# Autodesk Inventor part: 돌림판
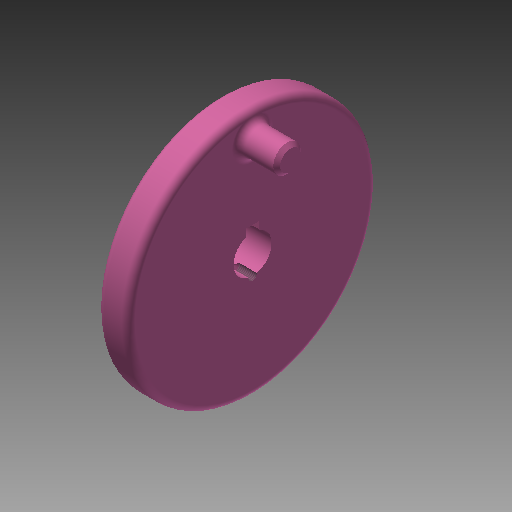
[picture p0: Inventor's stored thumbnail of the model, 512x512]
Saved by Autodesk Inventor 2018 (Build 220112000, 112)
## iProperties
Created: 2019-09
Part Number: 돌림판
Material: 알루미늄 6061
Document SubType Name: Modeling
Designer: mduedu
Density: 2.71 g/cm^3
Mass: 83.7231 g
Surface Area: 107.333 cm^2
Volume: 30.8941 cm^3
Appearance: 분홍색
Author: mduedu
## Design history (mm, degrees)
sketch "스케치1"
  geometry: L1 (0, 0)-(9, 0); L2 (9, 0)-(9, 36); L3 (9, 36)-(0, 36); L4 (0, 23)-(4, 23); L5 (4, 23)-(4, 10); L6 (4, 10)-(0, 10); L7 (0, 36)-(0, 23); L8 (0, 10)-(0, 0)
  constraints: 16 end point, 4 parallel, 2 horizontal, 2 perpendicular, 1 collinear
  dimensions: "d0" = 72 diameter of L3 L1; "d2" = 9 distance of L2.end L3.end; "d3" = 4 distance between parallel lines of L7 L5; "d4" = 20 diameter of L6 L1; "d5" = 46 diameter of L4 L1
revolve "회전1" sketch "스케치1" stored, may be unused: angle "d6" = 90 deg
fillet "모깎기1" dims "d7" = 3
sketch "스케치2"
  geometry: C1 r 4 at (0, 29); 1 further point
  constraints: 1 centre point, 1 vertical alignment
  dimensions: "d8" = 8 diameter of C1; "d9" = 29 distance of C1.centre point (0, 0)
extrude "돌출1" join sketch "스케치2" distance "d10" = 11; taper "d11" = 0 deg
fillet "모깎기2" dims "d12" = 2
fillet "모깎기3" dims "d13" = 2
chamfer "모따기1" distance "d14" = 1; stored, may be unused: second distance "d15" = 2, angle "d16" = 45 deg
sketch "스케치3"
  geometry: L1 (-2, 5.123)-(2, 5.123); L2 (2, 5.123)-(2, 7.3); L3 (2, 7.3)-(-2, 7.3); L4 (-2, 7.3)-(-2, 5.123); A1 r 5.5 centre (0, 0) between (-2, 5.123) and (2, 5.123); 1 further point
  constraints: 8 end point, 2 parallel, 2 point on circle, 1 centre point, 1 coincident, 1 horizontal, 1 perpendicular
  dimensions: "d17" = 11 diameter of A1; "d18" = 4 distance of L2.end L3.end; "d19" = 12.8 dimension on A1 L3
extrude "돌출2" cut sketch "스케치3" extent not by distance; stored distance "d20" = 11; taper "d21" = 0 deg
chamfer "모따기2" distance "d22" = 0.5; stored, may be unused: second distance "d23" = 2, angle "d24" = 45 deg
sketch "스케치4"
  geometry: A1 r 5.5 centre (0, 0) between (-2, 5.123) and (2, 5.123) reference; 2 further points
  constraints: 1 point on circle
hole "구멍1" sketch "스케치4" at (0, -5.5) diameter "d25" = 2.459; stored, may be unused: countersink angle "d29" = 90 deg, drill point angle "d31" = 118 deg; dims "d26" = 6, "d27" = 4, "d28" = 2, "d30" = 5
node "솔리드1"
